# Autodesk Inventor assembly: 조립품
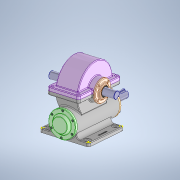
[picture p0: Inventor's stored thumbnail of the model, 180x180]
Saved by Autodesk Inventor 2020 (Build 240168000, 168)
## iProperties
Created: 2023-07
Part Number: 조립품
Document SubType Name: Assembly
Designer: home
Author: home
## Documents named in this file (13)
- C:\Users\home\Desktop\730706V1017\730706V1017\조립품.iam
- C:\Users\home\Desktop\730706V1017\본체.ipt
- C:\Users\home\Desktop\730706V1017\730706V1017\앞커버.ipt
- C:\Users\home\Desktop\730706V1017\730706V1017\뒤커버.ipt
- C:\Users\home\Desktop\730706V1017\730706V1017\깊은 홈 볼 베어링 6209.ipt
- C:\Users\home\Desktop\730706V1017\730706V1017\웜 샤프트.ipt
- C:\Users\home\Desktop\730706V1017\730706V1017\육각 소켓 머리 볼트 M5 x 12.ipt
- C:\Users\home\Desktop\730706V1017\730706V1017\서브커버.ipt
- C:\Users\home\Desktop\730706V1017\730706V1017\웜 휠.ipt
- C:\Users\home\Desktop\730706V1017\730706V1017\깊은 홈 볼 베어링 6206.ipt
- C:\Users\home\Desktop\730706V1017\730706V1017\본체 커버.ipt
- C:\Users\home\Desktop\730706V1017\730706V1017\오일 실 30 42 7.ipt
- C:\Users\home\Desktop\730706V1017\730706V1017\오일 실 35 55 11.ipt
